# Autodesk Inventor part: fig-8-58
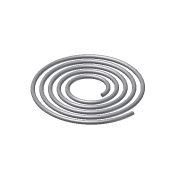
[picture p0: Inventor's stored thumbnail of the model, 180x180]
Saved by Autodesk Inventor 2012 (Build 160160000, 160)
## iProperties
Shininess: 77.0
Length Units: 11269
Angle Units: 11279
Time Units: 11290
Mass Units: 11283
Length Display Precision: 3
Angle Display Precision: 2
Created: 2002-01
Part Number: fig-8-58
Document SubType Name: Modeling
Designer: CADSoft
Density: 1 g/cm^3
Material: Default
Density: 0.0
Volumn: 0.0
Area: 0.0
PropertySet Name: Model Information
Control State: 0
Master: False
Checked Out: False
Author: CADSoft
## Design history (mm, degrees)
sketch "Sketch2"
  geometry: C1 r 2.5 at (-19.895, -0.092)
  constraints: 1 centre point
  dimensions: "d0" = 5 diameter of C1
coil "Coil5" sketch "Sketch2" pitch "d35" = 10; turns "d37" = 5; dims "d36" = 10, "d38" = 0, angle "d39" = 90 deg, angle "d40" = 90 deg, "d41" = 0, "d42" = 0
body "Solid1"
